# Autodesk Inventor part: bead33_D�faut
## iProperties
Created: 2011-01
Part Number: bead33_D�faut
Document SubType Name: Modeling
Designer: eric
Density: 1 g/cm^3
Mass: 0.0717662 g
Surface Area: 2.41971 cm^2
Volume: 0.0717662 cm^3
Author: eric
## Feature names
1. Base1
